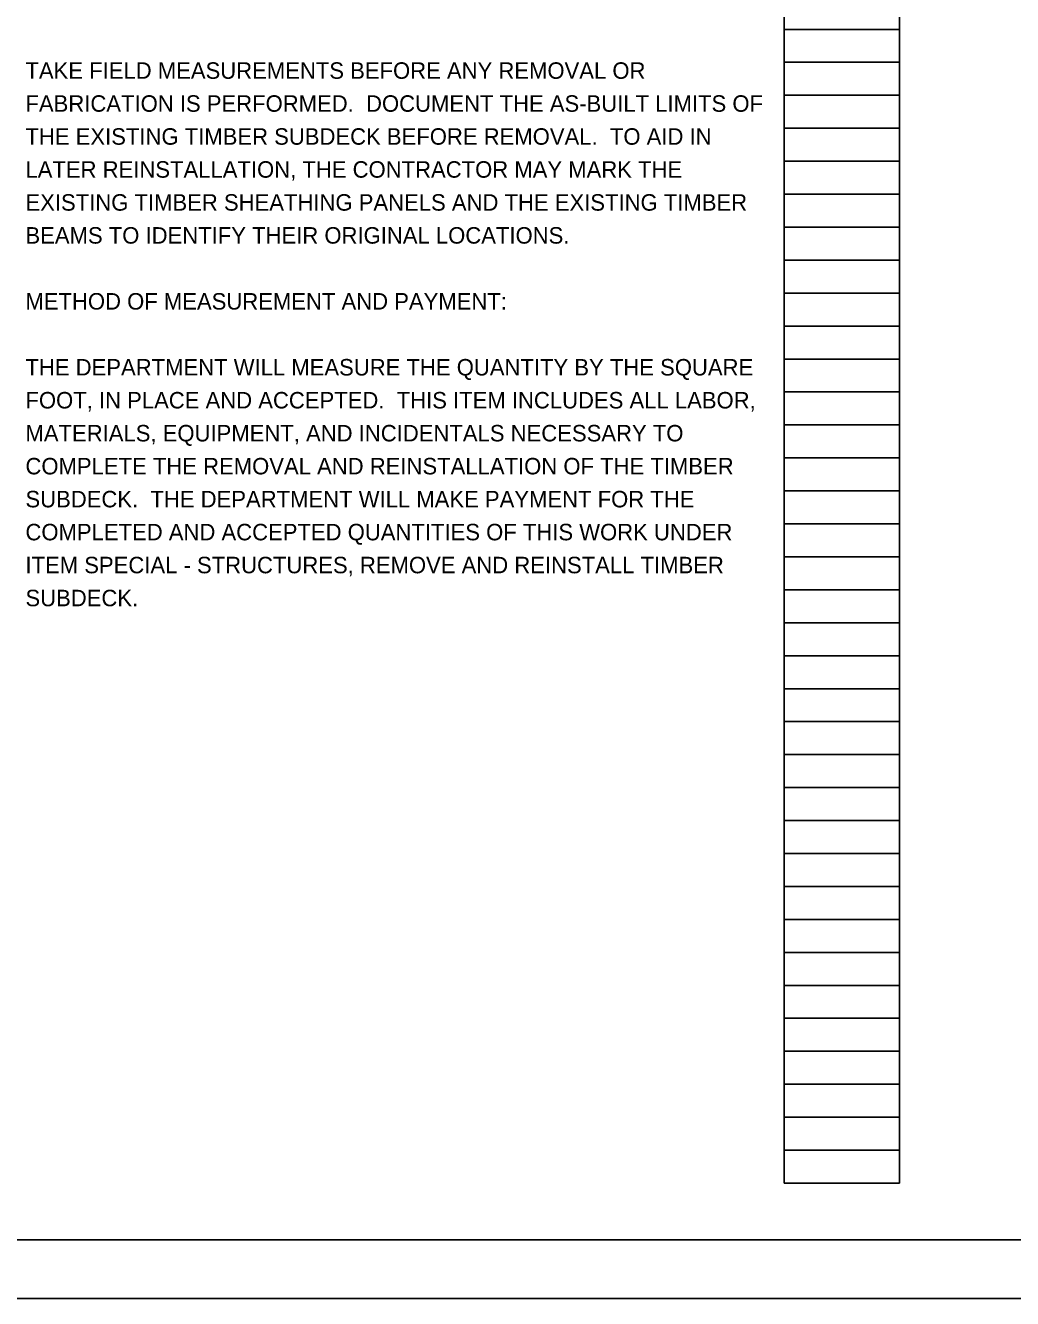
# Model space of a CAD drawing. Extents: x 0 to 65, y -0.7 to 22.
# Drawn here: x 17.24 to 25.62, y 0 to 10.81 of the extents above; entities that cross this region are included whole.
import ezdxf

# ---------------------------------------------------------------- set-up
doc = ezdxf.new("R2010")
doc.units = 0
for name, color, linetype in [('SH_Border', 7, 'Continuous'), ('SH_Cut_Line', 7, 'Continuous'), ('SH_Text', 7, 'Continuous')]:
    doc.layers.add(name, color=color, linetype=linetype)

msp = doc.modelspace()

# ---------------------------------------------------------------- linework, layer by layer
at = {"layer": 'SH_Border'}
for p, q in [((23.68, 0.98), (23.68, 21.14)), ((24.66, 0.98), (24.66, 21.14)), ((23.68, 10.78), (24.66, 10.78)), ((23.68, 10.5), (24.66, 10.5)), ((23.68, 10.22), (24.66, 10.22)), ((23.68, 9.94), (24.66, 9.94)), ((23.68, 9.66), (24.66, 9.66)), ((23.68, 9.38), (24.66, 9.38)), ((23.68, 9.1), (24.66, 9.1)), ((23.68, 8.82), (24.66, 8.82)), ((23.68, 8.54), (24.66, 8.54)), ((23.68, 8.26), (24.66, 8.26)), ((23.68, 7.98), (24.66, 7.98)), ((23.68, 7.7), (24.66, 7.7)), ((23.68, 7.42), (24.66, 7.42)), ((23.68, 7.14), (24.66, 7.14)), ((23.68, 6.86), (24.66, 6.86)), ((23.68, 6.58), (24.66, 6.58)), ((23.68, 6.3), (24.66, 6.3)), ((23.68, 6.02), (24.66, 6.02)), ((23.68, 5.74), (24.66, 5.74)), ((23.68, 5.46), (24.66, 5.46)), ((23.68, 5.18), (24.66, 5.18)), ((23.68, 4.9), (24.66, 4.9)), ((23.68, 4.62), (24.66, 4.62)), ((23.68, 4.34), (24.66, 4.34)), ((23.68, 4.06), (24.66, 4.06)), ((23.68, 3.78), (24.66, 3.78)), ((23.68, 3.5), (24.66, 3.5)), ((23.68, 3.22), (24.66, 3.22)), ((23.68, 2.94), (24.66, 2.94)), ((23.68, 2.66), (24.66, 2.66)), ((23.68, 2.38), (24.66, 2.38)), ((23.68, 2.1), (24.66, 2.1)), ((23.68, 1.82), (24.66, 1.82)), ((23.68, 1.54), (24.66, 1.54)), ((23.68, 1.26), (24.66, 1.26)), ((23.68, 0.98), (24.66, 0.98))]:
    msp.add_line(p, q, dxfattribs=at)
at = {"layer": 'SH_Cut_Line'}
msp.add_lwpolyline([(1.5, 21.5), (33.5, 21.5), (33.5, 0.5), (1.5, 0.5)], close=True, dxfattribs=at)
at = {"layer": 'SH_Text'}
msp.add_lwpolyline([(0, 0), (34, 0), (34, 22), (0, 22)], close=True, dxfattribs=at)

# ---------------------------------------------------------------- texts
for s, p in [('TAKE FIELD MEASUREMENTS BEFORE ANY REMOVAL OR ', (17.24, 10.36)), ('FABRICATION IS PERFORMED.  DOCUMENT THE AS-BUILT LIMITS OF ', (17.24, 10.08)), ('THE EXISTING TIMBER SUBDECK BEFORE REMOVAL.  TO AID IN ', (17.24, 9.8)), ('LATER REINSTALLATION, THE CONTRACTOR MAY MARK THE ', (17.24, 9.52)), ('EXISTING TIMBER SHEATHING PANELS AND THE EXISTING TIMBER ', (17.24, 9.24)), ('BEAMS TO IDENTIFY THEIR ORIGINAL LOCATIONS. ', (17.24, 8.96)), ('METHOD OF MEASUREMENT AND PAYMENT:', (17.24, 8.4)), ('THE DEPARTMENT WILL MEASURE THE QUANTITY BY THE SQUARE ', (17.24, 7.84)), ('FOOT, IN PLACE AND ACCEPTED.  THIS ITEM INCLUDES ALL LABOR, ', (17.24, 7.56)), ('MATERIALS, EQUIPMENT, AND INCIDENTALS NECESSARY TO ', (17.24, 7.28)), ('COMPLETE THE REMOVAL AND REINSTALLATION OF THE TIMBER ', (17.24, 7)), ('SUBDECK.  THE DEPARTMENT WILL MAKE PAYMENT FOR THE ', (17.24, 6.72)), ('COMPLETED AND ACCEPTED QUANTITIES OF THIS WORK UNDER ', (17.24, 6.44)), ('ITEM SPECIAL - STRUCTURES, REMOVE AND REINSTALL TIMBER ', (17.24, 6.16)), ('SUBDECK.', (17.24, 5.88))]:
    msp.add_text(s, height=0.14, dxfattribs=at).set_placement(p)

doc.saveas('drawing.dxf')
